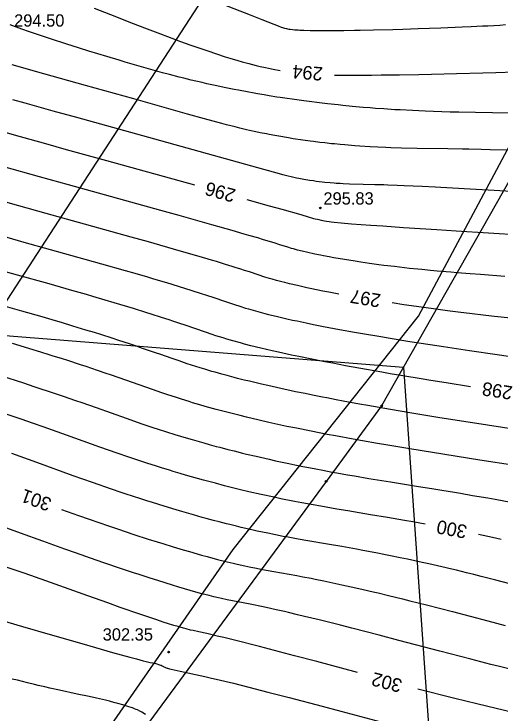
# Model space of a CAD drawing. Extents: x 7477803 to 7478145, y 5500698 to 5500984.
# Drawn here: x 7477874.58 to 7477901.52, y 5500853.98 to 5500892.73 of the extents above; entities that cross this region are included whole.
import ezdxf

# ---------------------------------------------------------------- set-up
doc = ezdxf.new("R2010")
doc.units = 0
for name, color, linetype in [('203-Punkt załamania granicy działki nie stabilizowany', 7, 'Continuous'), ('eWN', 7, 'Continuous'), ('gr_dzialki', 7, 'Continuous'), ('gr_klasy', 7, 'Continuous'), ('pkt_wys', 7, 'Continuous'), ('warst_ciagla', 7, 'Continuous'), ('warst_opis', 7, 'Continuous'), ('warst_pogrub', 7, 'Continuous'), ('warst_przeryw', 7, 'Continuous')]:
    doc.layers.add(name, color=color, linetype=linetype)

# ---------------------------------------------------------------- blocks, each defined once
blk = doc.blocks.new('203')
blk.add_circle((0, 0), 0.045)
blk = doc.blocks.new('801_3')
at = {"layer": 'pkt_wys'}
blk.add_circle((0, 0), 0.045, dxfattribs=at)
blk.add_circle((0, 0), 0.045, dxfattribs=at)

msp = doc.modelspace()

# ---------------------------------------------------------------- linework, layer by layer
at = {"layer": 'eWN'}
msp.add_lwpolyline([(7477864.586, 5500830.869), (7477874.504, 5500845.51), (7477886.717, 5500863.094), (7477896.968, 5500876.013), (7477903.181, 5500887.651), (7477907.573, 5500896.009), (7477910.052, 5500901.721), (7477911.094, 5500907.132), (7477899.209, 5500916.554), (7477885.259, 5500927.591), (7477881.972, 5500929.954), (7477875.911, 5500934.547), (7477875.795, 5500934.654)], dxfattribs=at)
at = {"layer": 'gr_dzialki'}
for points in [[(7477867.65, 5500866.83), (7477899.54, 5500915.94)], [(7477908.77, 5500895.48), (7477894.92, 5500871.04)], [(7477894.92, 5500871.04), (7477891.85, 5500866.86)], [(7477891.85, 5500866.86), (7477876.54, 5500846.03)]]:
    msp.add_lwpolyline(points, dxfattribs=at)
at = {"layer": 'gr_klasy'}
for points in [[(7477840.435, 5500877.607), (7477896.14, 5500873.19)], [(7477896.14, 5500873.19), (7477899.58, 5500823.8)]]:
    msp.add_lwpolyline(points, dxfattribs=at)
at = {"layer": 'warst_ciagla'}
for points in [[(7477879.025, 5500893.052), (7477879.924, 5500892.701), (7477881.178, 5500892.21), (7477881.798, 5500891.97), (7477882.689, 5500891.63), (7477883.069, 5500891.487), (7477883.56, 5500891.306), (7477883.798, 5500891.218), (7477884.319, 5500891.03), (7477884.981, 5500890.797), (7477885.304, 5500890.687), (7477885.784, 5500890.527), (7477886.269, 5500890.371), (7477886.515, 5500890.294), (7477886.966, 5500890.158), (7477887.203, 5500890.09), (7477887.577, 5500889.988), (7477887.982, 5500889.886), (7477888.199, 5500889.836), (7477888.504, 5500889.768), (7477888.664, 5500889.735), (7477888.915, 5500889.684), (7477889.317, 5500889.609)], [(7477892.306, 5500889.354), (7477892.728, 5500889.351), (7477893.559, 5500889.349), (7477894.37, 5500889.353), (7477894.896, 5500889.357), (7477895.909, 5500889.37), (7477896.982, 5500889.388), (7477897.674, 5500889.401), (7477899.066, 5500889.435), (7477900.519, 5500889.475), (7477901.244, 5500889.497), (7477902.289, 5500889.532)], [(7477873.093, 5500886.469), (7477874.585, 5500886.046), (7477876.329, 5500885.556), (7477877.474, 5500885.236), (7477879.697, 5500884.618), (7477884.565, 5500883.269)], [(7477892.549, 5500877.23), (7477892.007, 5500877.332), (7477891.671, 5500877.398), (7477891.059, 5500877.522), (7477890.78, 5500877.581), (7477890.274, 5500877.694), (7477889.829, 5500877.799), (7477889.564, 5500877.865), (7477889.399, 5500877.907), (7477889.097, 5500877.988), (7477888.867, 5500878.052), (7477888.725, 5500878.093), (7477888.459, 5500878.173), (7477888.091, 5500878.29), (7477887.604, 5500878.451), (7477887.339, 5500878.538), (7477887.123, 5500878.607), (7477886.812, 5500878.706), (7477886.645, 5500878.758), (7477886.292, 5500878.867), (7477885.777, 5500879.023), (7477885.502, 5500879.105), (7477884.836, 5500879.302), (7477883.721, 5500879.627), (7477882.015, 5500880.113), (7477881.068, 5500880.38), (7477876.367, 5500881.69), (7477874.851, 5500882.116), (7477872.954, 5500882.653)], [(7477887.456, 5500882.466), (7477888.704, 5500882.119), (7477889.409, 5500881.921), (7477890.446, 5500881.628), (7477890.864, 5500881.507), (7477891.097, 5500881.437), (7477891.153, 5500881.421), (7477891.24, 5500881.398), (7477891.376, 5500881.366), (7477891.453, 5500881.349), (7477891.579, 5500881.324), (7477891.768, 5500881.29), (7477891.872, 5500881.272), (7477892.026, 5500881.248), (7477892.121, 5500881.234), (7477892.299, 5500881.213), (7477892.684, 5500881.174), (7477893.254, 5500881.126), (7477894.318, 5500881.046), (7477894.981, 5500880.999), (7477896.137, 5500880.92), (7477897.983, 5500880.799), (7477899.036, 5500880.731), (7477902.624, 5500880.502)], [(7477899.834, 5500872.098), (7477898.484, 5500872.31), (7477897.644, 5500872.445), (7477897.109, 5500872.532), (7477896.099, 5500872.7), (7477895.39, 5500872.821), (7477894.939, 5500872.899), (7477894.088, 5500873.049), (7477892.927, 5500873.262), (7477892.224, 5500873.395), (7477891.784, 5500873.48), (7477890.966, 5500873.643), (7477890.333, 5500873.772), (7477889.938, 5500873.855), (7477889.208, 5500874.013), (7477888.871, 5500874.088), (7477888.247, 5500874.233), (7477887.682, 5500874.372), (7477887.335, 5500874.462), (7477887.114, 5500874.52), (7477886.697, 5500874.636), (7477886.366, 5500874.733), (7477886.154, 5500874.797), (7477885.749, 5500874.924), (7477885.554, 5500874.988), (7477885.173, 5500875.115), (7477884.053, 5500875.499), (7477883.764, 5500875.597), (7477883.367, 5500875.73), (7477883.164, 5500875.797), (7477882.748, 5500875.933), (7477882.175, 5500876.116), (7477881.881, 5500876.209), (7477881.198, 5500876.422), (7477880.122, 5500876.749), (7477879.624, 5500876.898), (7477878.941, 5500877.099), (7477878.591, 5500877.201), (7477877.784, 5500877.433), (7477876.525, 5500877.789), (7477874.785, 5500878.276), (7477873.902, 5500878.524)], [(7477902.061, 5500875.897), (7477901.168, 5500875.993), (7477900.692, 5500876.046), (7477899.787, 5500876.152), (7477899.309, 5500876.211), (7477898.564, 5500876.305), (7477897.786, 5500876.408), (7477897.386, 5500876.463), (7477896.566, 5500876.579), (7477896.147, 5500876.641), (7477895.508, 5500876.737)], [(7477902.285, 5500867.731), (7477900.354, 5500868.042), (7477897.741, 5500868.46), (7477896.473, 5500868.666), (7477895.262, 5500868.866), (7477894.687, 5500868.963), (7477893.866, 5500869.104), (7477893.346, 5500869.196), (7477892.367, 5500869.373), (7477891.904, 5500869.46), (7477891.027, 5500869.63), (7477890.204, 5500869.796), (7477889.681, 5500869.906), (7477889.342, 5500869.979), (7477888.681, 5500870.125), (7477888.139, 5500870.249), (7477887.437, 5500870.416), (7477887.095, 5500870.5), (7477886.427, 5500870.67), (7477886.138, 5500870.745), (7477885.759, 5500870.847), (7477885.573, 5500870.898), (7477885.161, 5500871.013), (7477884.859, 5500871.1), (7477884.466, 5500871.216), (7477884.273, 5500871.274), (7477883.848, 5500871.407), (7477883.571, 5500871.495), (7477883.032, 5500871.672), (7477882.769, 5500871.761), (7477882.253, 5500871.938), (7477880.767, 5500872.46), (7477880.404, 5500872.587), (7477879.922, 5500872.754), (7477879.682, 5500872.836), (7477879.205, 5500872.998), (7477878.573, 5500873.21), (7477878.26, 5500873.314), (7477877.56, 5500873.542), (7477877.213, 5500873.654), (7477876.752, 5500873.8), (7477876.523, 5500873.872), (7477876.068, 5500874.014), (7477875.466, 5500874.198), (7477875.167, 5500874.288), (7477874.499, 5500874.486)], [(7477877.202, 5500865.3), (7477878.15, 5500864.965), (7477878.738, 5500864.76), (7477879.812, 5500864.391), (7477880.303, 5500864.225), (7477881.204, 5500863.927), (7477882.008, 5500863.667), (7477882.499, 5500863.512), (7477882.809, 5500863.416), (7477883.394, 5500863.238), (7477883.95, 5500863.071), (7477884.3, 5500862.969), (7477884.956, 5500862.782), (7477885.263, 5500862.697), (7477885.84, 5500862.542), (7477886.375, 5500862.406), (7477886.711, 5500862.325), (7477886.928, 5500862.275), (7477887.345, 5500862.182), (7477887.684, 5500862.11), (7477887.904, 5500862.066), (7477888.335, 5500861.983), (7477888.966, 5500861.868), (7477889.805, 5500861.72), (7477890.236, 5500861.643), (7477890.567, 5500861.581), (7477891.021, 5500861.493), (7477891.253, 5500861.447), (7477891.728, 5500861.351), (7477892.383, 5500861.213), (7477892.72, 5500861.14), (7477893.501, 5500860.967), (7477893.903, 5500860.875), (7477894.452, 5500860.748), (7477894.731, 5500860.682), (7477895.301, 5500860.546), (7477896.082, 5500860.355), (7477896.482, 5500860.255), (7477897.405, 5500860.022), (7477898.841, 5500859.65), (7477900.789, 5500859.139), (7477901.747, 5500858.889)], [(7477893.589, 5500856.284), (7477891.333, 5500856.881), (7477890.098, 5500857.205), (7477888.156, 5500857.71), (7477886.85, 5500858.043), (7477886.188, 5500858.209), (7477885.826, 5500858.297), (7477885.26, 5500858.431), (7477884.81, 5500858.53), (7477884.497, 5500858.597), (7477884.347, 5500858.631), (7477884.105, 5500858.691), (7477883.968, 5500858.728), (7477883.767, 5500858.785), (7477883.658, 5500858.817), (7477883.424, 5500858.887), (7477883.078, 5500858.995), (7477882.89, 5500859.055), (7477882.433, 5500859.204), (7477881.656, 5500859.466), (7477881.275, 5500859.597), (7477880.733, 5500859.785), (7477880.448, 5500859.886), (7477879.77, 5500860.126), (7477878.671, 5500860.52), (7477877.118, 5500861.078), (7477876.337, 5500861.357), (7477875.193, 5500861.759), (7477874.696, 5500861.931), (7477874.045, 5500862.155)], [(7477881.867, 5500853.962), (7477881.663, 5500854.078), (7477881.548, 5500854.14), (7477881.415, 5500854.203), (7477881.339, 5500854.236), (7477881.256, 5500854.27), (7477881.135, 5500854.315), (7477881.069, 5500854.339), (7477880.928, 5500854.386), (7477880.721, 5500854.452), (7477880.608, 5500854.485), (7477880.335, 5500854.563), (7477880.187, 5500854.602), (7477879.979, 5500854.657), (7477879.87, 5500854.684), (7477879.643, 5500854.74), (7477879.319, 5500854.817), (7477879.149, 5500854.856), (7477878.746, 5500854.946), (7477878.086, 5500855.087), (7477877.107, 5500855.296), (7477876.574, 5500855.414), (7477876.297, 5500855.478), (7477875.917, 5500855.567), (7477875.722, 5500855.613), (7477875.323, 5500855.71), (7477874.771, 5500855.846), (7477874.487, 5500855.918)], [(7477902.26, 5500854.048), (7477900.187, 5500854.55), (7477898.977, 5500854.845), (7477896.921, 5500855.351)]]:
    msp.add_lwpolyline(points, dxfattribs=at)
at = {"layer": 'warst_pogrub'}
for points in [[(7477902.022, 5500885.194), (7477900.935, 5500885.222), (7477900.432, 5500885.233), (7477899.744, 5500885.247), (7477899.391, 5500885.253), (7477898.579, 5500885.266), (7477896.884, 5500885.292), (7477896.017, 5500885.311), (7477895.438, 5500885.329), (7477895.149, 5500885.339), (7477894.718, 5500885.358), (7477894.289, 5500885.381), (7477893.722, 5500885.417), (7477893.44, 5500885.437), (7477892.881, 5500885.482), (7477892.634, 5500885.505), (7477892.306, 5500885.537), (7477892.143, 5500885.553), (7477891.778, 5500885.593), (7477891.505, 5500885.625), (7477891.144, 5500885.67), (7477890.964, 5500885.694), (7477890.562, 5500885.749), (7477890.03, 5500885.829), (7477889.766, 5500885.872), (7477889.242, 5500885.962), (7477889.01, 5500886.004), (7477888.704, 5500886.062), (7477888.551, 5500886.092), (7477888.209, 5500886.161), (7477887.954, 5500886.215), (7477887.617, 5500886.29), (7477887.449, 5500886.328), (7477887.073, 5500886.417), (7477886.824, 5500886.478), (7477886.33, 5500886.604), (7477886.085, 5500886.668), (7477885.6, 5500886.799), (7477885.121, 5500886.931), (7477884.182, 5500887.196), (7477881.211, 5500888.036), (7477878.547, 5500888.782), (7477876.237, 5500889.423), (7477874.474, 5500889.915)], [(7477897.33, 5500864.49), (7477896.647, 5500864.612), (7477896.183, 5500864.693), (7477895.243, 5500864.853), (7477894.298, 5500865.012), (7477893.05, 5500865.221), (7477892.44, 5500865.324), (7477891.553, 5500865.479), (7477891.125, 5500865.555), (7477890.507, 5500865.67), (7477890.11, 5500865.746), (7477889.345, 5500865.899), (7477888.976, 5500865.976), (7477888.261, 5500866.131), (7477887.569, 5500866.289), (7477887.117, 5500866.397), (7477886.819, 5500866.471), (7477886.226, 5500866.62), (7477885.727, 5500866.751), (7477885.063, 5500866.93), (7477884.732, 5500867.022), (7477884.069, 5500867.212), (7477883.775, 5500867.298), (7477883.384, 5500867.415), (7477883.188, 5500867.474), (7477882.748, 5500867.61), (7477882.419, 5500867.714), (7477881.98, 5500867.855), (7477881.761, 5500867.926), (7477881.268, 5500868.09), (7477880.94, 5500868.2), (7477880.289, 5500868.424), (7477879.326, 5500868.762), (7477877.481, 5500869.421), (7477876.2, 5500869.875), (7477875.661, 5500870.064), (7477874.971, 5500870.303), (7477874.639, 5500870.418), (7477873.922, 5500870.662)], [(7477901.539, 5500863.64), (7477901.057, 5500863.749), (7477900.275, 5500863.921)]]:
    msp.add_lwpolyline(points, dxfattribs=at)
at = {"layer": 'warst_przeryw'}
for points in [[(7477884.938, 5500893.751), (7477887.644, 5500892.684), (7477888.29, 5500892.431), (7477888.952, 5500892.173), (7477889.197, 5500892.079), (7477889.371, 5500892.013), (7477889.446, 5500891.987), (7477889.552, 5500891.953), (7477889.656, 5500891.925), (7477889.709, 5500891.914), (7477889.794, 5500891.899), (7477889.856, 5500891.89), (7477889.993, 5500891.874), (7477890.113, 5500891.863), (7477890.297, 5500891.851), (7477890.399, 5500891.846), (7477890.623, 5500891.837), (7477890.963, 5500891.827), (7477891.151, 5500891.824), (7477891.618, 5500891.819), (7477891.874, 5500891.819), (7477892.239, 5500891.82), (7477892.431, 5500891.821), (7477892.837, 5500891.825), (7477893.419, 5500891.833), (7477893.728, 5500891.838), (7477894.467, 5500891.853), (7477895.537, 5500891.88), (7477896.096, 5500891.896), (7477896.945, 5500891.922), (7477898.2, 5500891.966), (7477899.376, 5500892.015), (7477899.869, 5500892.038), (7477900.499, 5500892.07), (7477900.802, 5500892.086), (7477901.455, 5500892.124), (7477901.766, 5500892.144)], [(7477902.906, 5500887.238), (7477901.054, 5500887.262), (7477900.122, 5500887.277), (7477899.188, 5500887.296), (7477898.722, 5500887.307), (7477897.792, 5500887.336), (7477897.329, 5500887.353), (7477896.637, 5500887.383), (7477895.95, 5500887.419), (7477895.646, 5500887.437), (7477895.242, 5500887.463), (7477895.041, 5500887.476), (7477894.59, 5500887.509), (7477894.29, 5500887.532), (7477893.892, 5500887.565), (7477893.693, 5500887.582), (7477893.298, 5500887.618), (7477892.772, 5500887.669), (7477892.511, 5500887.696), (7477891.926, 5500887.76), (7477891.489, 5500887.811), (7477890.91, 5500887.883), (7477890.622, 5500887.92), (7477889.977, 5500888.01), (7477889.692, 5500888.051), (7477889.313, 5500888.109), (7477889.125, 5500888.138), (7477888.702, 5500888.206), (7477888.421, 5500888.253), (7477888.048, 5500888.317), (7477887.862, 5500888.35), (7477887.491, 5500888.417), (7477887, 5500888.511), (7477886.755, 5500888.558), (7477886.207, 5500888.67), (7477885.799, 5500888.756), (7477885.258, 5500888.876), (7477884.989, 5500888.937), (7477884.386, 5500889.079), (7477883.987, 5500889.177), (7477883.722, 5500889.244), (7477883.195, 5500889.38), (7477882.802, 5500889.484), (7477882.021, 5500889.698), (7477881.248, 5500889.919), (7477880.736, 5500890.068), (7477880.396, 5500890.169), (7477879.721, 5500890.372), (7477878.715, 5500890.683), (7477878.21, 5500890.842), (7477877.445, 5500891.087), (7477876.664, 5500891.344), (7477876.265, 5500891.477), (7477875.444, 5500891.755), (7477875.021, 5500891.901), (7477874.368, 5500892.129)], [(7477902.765, 5500882.862), (7477900.823, 5500882.979), (7477899.488, 5500883.056), (7477897.888, 5500883.141), (7477897.165, 5500883.178), (7477896.176, 5500883.223), (7477895.773, 5500883.24), (7477895.272, 5500883.26), (7477895.036, 5500883.268), (7477894.543, 5500883.284), (7477893.893, 5500883.3), (7477893.145, 5500883.32), (7477892.799, 5500883.334), (7477892.628, 5500883.343), (7477892.403, 5500883.357), (7477892.291, 5500883.365), (7477892.068, 5500883.383), (7477891.775, 5500883.411), (7477891.63, 5500883.427), (7477891.306, 5500883.467), (7477891.146, 5500883.489), (7477890.935, 5500883.521), (7477890.83, 5500883.538), (7477890.621, 5500883.574), (7477890.347, 5500883.625), (7477890.211, 5500883.653), (7477889.909, 5500883.719), (7477889.759, 5500883.755), (7477889.456, 5500883.831), (7477889.138, 5500883.916), (7477888.4, 5500884.122), (7477885.959, 5500884.804), (7477882.381, 5500885.797), (7477878.053, 5500886.996), (7477876.745, 5500887.36), (7477875.208, 5500887.791), (7477874.527, 5500887.982)], [(7477901.73, 5500878.206), (7477900.391, 5500878.304), (7477899.825, 5500878.348), (7477899.099, 5500878.407), (7477898.747, 5500878.436), (7477897.985, 5500878.504), (7477897.619, 5500878.538), (7477897.146, 5500878.583), (7477896.917, 5500878.606), (7477896.471, 5500878.653), (7477895.904, 5500878.715), (7477895.633, 5500878.746), (7477895.051, 5500878.817), (7477894.775, 5500878.852), (7477894.251, 5500878.924), (7477893.762, 5500878.996), (7477893.453, 5500879.044), (7477892.871, 5500879.138), (7477892.268, 5500879.243), (7477892.017, 5500879.288), (7477891.698, 5500879.348), (7477891.546, 5500879.378), (7477891.22, 5500879.443), (7477890.774, 5500879.54), (7477890.592, 5500879.582), (7477890.367, 5500879.637), (7477890.261, 5500879.664), (7477890.039, 5500879.725), (7477889.937, 5500879.755), (7477889.738, 5500879.816), (7477889.283, 5500879.963), (7477888.982, 5500880.058), (7477888.386, 5500880.238), (7477888.064, 5500880.334), (7477887.578, 5500880.476), (7477887.312, 5500880.553), (7477886.655, 5500880.742), (7477885.52, 5500881.065), (7477883.727, 5500881.57), (7477882.711, 5500881.853), (7477877.6, 5500883.274), (7477875.988, 5500883.724), (7477874.028, 5500884.276)], [(7477874.182, 5500880.375), (7477875.135, 5500880.107), (7477876.588, 5500879.701), (7477878.507, 5500879.165), (7477879.426, 5500878.907), (7477880.724, 5500878.536), (7477881.269, 5500878.379), (7477881.964, 5500878.176), (7477882.298, 5500878.077), (7477883.017, 5500877.862), (7477884.011, 5500877.559), (7477884.421, 5500877.431), (7477884.936, 5500877.267), (7477885.18, 5500877.189), (7477885.696, 5500877.019), (7477886.171, 5500876.858), (7477886.775, 5500876.654), (7477887.079, 5500876.555), (7477887.393, 5500876.456), (7477887.556, 5500876.407), (7477887.811, 5500876.332), (7477888.08, 5500876.257), (7477888.461, 5500876.156), (7477888.661, 5500876.105), (7477889.081, 5500876.002), (7477889.681, 5500875.863), (7477889.998, 5500875.792), (7477890.243, 5500875.739), (7477890.58, 5500875.667), (7477890.753, 5500875.631), (7477891.153, 5500875.55), (7477891.708, 5500875.44), (7477891.995, 5500875.384), (7477892.589, 5500875.273), (7477893.421, 5500875.122), (7477893.854, 5500875.045), (7477894.87, 5500874.871), (7477895.4, 5500874.783), (7477896.49, 5500874.607), (7477897.601, 5500874.432), (7477898.341, 5500874.319), (7477899.786, 5500874.101), (7477901.309, 5500873.88), (7477901.947, 5500873.79)], [(7477902.675, 5500869.672), (7477899.7, 5500870.136), (7477898.143, 5500870.384), (7477896.598, 5500870.636), (7477895.843, 5500870.763), (7477895.107, 5500870.889), (7477894.156, 5500871.056), (7477893.692, 5500871.139), (7477892.792, 5500871.305), (7477892.403, 5500871.378), (7477891.894, 5500871.476), (7477891.644, 5500871.524), (7477891.093, 5500871.633), (7477890.69, 5500871.715), (7477890.165, 5500871.823), (7477889.909, 5500871.877), (7477889.345, 5500871.999), (7477888.624, 5500872.159), (7477888.276, 5500872.239), (7477887.606, 5500872.399), (7477887.319, 5500872.469), (7477886.947, 5500872.563), (7477886.765, 5500872.609), (7477886.368, 5500872.714), (7477886.08, 5500872.793), (7477885.709, 5500872.897), (7477885.529, 5500872.949), (7477885.138, 5500873.065), (7477884.887, 5500873.142), (7477884.404, 5500873.296), (7477884.17, 5500873.373), (7477883.717, 5500873.526), (7477883.276, 5500873.678), (7477882.699, 5500873.879), (7477882.41, 5500873.98), (7477882.084, 5500874.092), (7477881.644, 5500874.242), (7477881.423, 5500874.317), (7477880.976, 5500874.465), (7477880.374, 5500874.663), (7477880.07, 5500874.762), (7477879.379, 5500874.982), (7477879.029, 5500875.092), (7477878.559, 5500875.238), (7477878.323, 5500875.311), (7477877.846, 5500875.456), (7477877.203, 5500875.649), (7477876.879, 5500875.745), (7477876.879, 5500875.745), (7477876.142, 5500875.96), (7477875.016, 5500876.281), (7477872.67, 5500876.94)], [(7477874.183, 5500872.606), (7477874.761, 5500872.422), (7477875.057, 5500872.326), (7477875.741, 5500872.102), (7477876.813, 5500871.743), (7477877.308, 5500871.574), (7477877.984, 5500871.341), (7477878.329, 5500871.22), (7477879.124, 5500870.941), (7477880.789, 5500870.35), (7477881.66, 5500870.048), (7477882.256, 5500869.848), (7477882.558, 5500869.748), (7477883.017, 5500869.6), (7477883.482, 5500869.455), (7477884.114, 5500869.264), (7477884.434, 5500869.171), (7477885.084, 5500868.986), (7477885.377, 5500868.905), (7477885.77, 5500868.799), (7477885.969, 5500868.747), (7477886.42, 5500868.63), (7477886.761, 5500868.543), (7477887.221, 5500868.429), (7477887.454, 5500868.373), (7477887.981, 5500868.248), (7477888.694, 5500868.085), (7477889.056, 5500868.005), (7477889.787, 5500867.848), (7477890.116, 5500867.779), (7477890.559, 5500867.689), (7477890.782, 5500867.645), (7477891.287, 5500867.546), (7477891.67, 5500867.473), (7477892.185, 5500867.377), (7477892.444, 5500867.33), (7477893.032, 5500867.226), (7477893.427, 5500867.158), (7477894.22, 5500867.024), (7477895.406, 5500866.829), (7477896.953, 5500866.58), (7477897.699, 5500866.46), (7477898.243, 5500866.372), (7477898.944, 5500866.255), (7477899.286, 5500866.198), (7477899.949, 5500866.086), (7477900.792, 5500865.939), (7477901.197, 5500865.867), (7477902.065, 5500865.71)], [(7477903.638, 5500860.768), (7477901.247, 5500861.391), (7477900.43, 5500861.6), (7477900.021, 5500861.703), (7477899.612, 5500861.804), (7477899.068, 5500861.936), (7477898.796, 5500862.001), (7477898.252, 5500862.128), (7477897.529, 5500862.292), (7477897.167, 5500862.373), (7477896.356, 5500862.548), (7477895.95, 5500862.633), (7477895.411, 5500862.743), (7477895.141, 5500862.797), (7477894.603, 5500862.903), (7477893.886, 5500863.039), (7477893.528, 5500863.105), (7477892.724, 5500863.248), (7477891.92, 5500863.386), (7477890.842, 5500863.568), (7477890.297, 5500863.663), (7477889.745, 5500863.763), (7477889.467, 5500863.815), (7477889.045, 5500863.898), (7477888.617, 5500863.985), (7477888.039, 5500864.11), (7477887.746, 5500864.175), (7477887.152, 5500864.313), (7477886.885, 5500864.378), (7477886.527, 5500864.466), (7477886.346, 5500864.512), (7477885.936, 5500864.617), (7477885.626, 5500864.698), (7477885.209, 5500864.81), (7477884.998, 5500864.868), (7477884.521, 5500865.001), (7477883.876, 5500865.187), (7477883.55, 5500865.283), (7477883.55, 5500865.283), (7477882.89, 5500865.483), (7477882.594, 5500865.574), (7477882.196, 5500865.699), (7477881.996, 5500865.763), (7477881.542, 5500865.909), (7477881.198, 5500866.021), (7477880.737, 5500866.174), (7477880.504, 5500866.252), (7477879.978, 5500866.431), (7477878.917, 5500866.8), (7477877.862, 5500867.174), (7477875.838, 5500867.902), (7477874.459, 5500868.395)], [(7477902.386, 5500856.365), (7477901.444, 5500856.602), (7477900.963, 5500856.725), (7477899.857, 5500857.009), (7477898.148, 5500857.456), (7477895.875, 5500858.056), (7477894.789, 5500858.341), (7477893.27, 5500858.733), (7477892.639, 5500858.893), (7477891.84, 5500859.094), (7477891.459, 5500859.188), (7477890.646, 5500859.386), (7477890.262, 5500859.478), (7477889.775, 5500859.593), (7477889.541, 5500859.647), (7477889.095, 5500859.749), (7477888.542, 5500859.871), (7477888.284, 5500859.926), (7477887.748, 5500860.037), (7477887.268, 5500860.13), (7477886.672, 5500860.243), (7477886.374, 5500860.302), (7477886.064, 5500860.368), (7477885.901, 5500860.405), (7477885.645, 5500860.465), (7477885.372, 5500860.533), (7477884.98, 5500860.636), (7477884.772, 5500860.693), (7477884.332, 5500860.818), (7477883.697, 5500861.005), (7477883.358, 5500861.108), (7477882.543, 5500861.363), (7477882.109, 5500861.503), (7477881.502, 5500861.701), (7477881.187, 5500861.805), (7477880.533, 5500862.025), (7477879.611, 5500862.339), (7477879.129, 5500862.506), (7477877.992, 5500862.904), (7477877.398, 5500863.114), (7477876.174, 5500863.552), (7477874.934, 5500863.999), (7477872.553, 5500864.862)], [(7477872.727, 5500859.509), (7477875.047, 5500858.832), (7477876.589, 5500858.383), (7477878.339, 5500857.877), (7477879.083, 5500857.663), (7477880.035, 5500857.392), (7477881, 5500857.123), (7477881.352, 5500857.028), (7477881.725, 5500856.932), (7477881.895, 5500856.891), (7477882.125, 5500856.84), (7477882.262, 5500856.809), (7477882.422, 5500856.77), (7477882.492, 5500856.752), (7477882.584, 5500856.725), (7477882.684, 5500856.692), (7477882.724, 5500856.676), (7477882.772, 5500856.654), (7477882.845, 5500856.613), (7477882.881, 5500856.594), (7477882.931, 5500856.57), (7477882.957, 5500856.558), (7477882.997, 5500856.541), (7477883.053, 5500856.52), (7477883.083, 5500856.511), (7477883.191, 5500856.479), (7477883.28, 5500856.458), (7477883.775, 5500856.346), (7477884.626, 5500856.163), (7477885.134, 5500856.054), (7477885.443, 5500855.985), (7477886.009, 5500855.853), (7477886.725, 5500855.679), (7477887.923, 5500855.379), (7477888.627, 5500855.198), (7477889.813, 5500854.891), (7477891.638, 5500854.413), (7477892.656, 5500854.144), (7477894.874, 5500853.555)]]:
    msp.add_lwpolyline(points, dxfattribs=at)

# ---------------------------------------------------------------- block references
at = {"layer": '203-Punkt załamania granicy działki nie stabilizowany'}
for p in [(7477894.92, 5500871.04), (7477891.85, 5500866.86)]:
    msp.add_blockref('203', p, dxfattribs=at)
at = {"layer": 'pkt_wys', "rotation": 0.0626175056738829}
for p in [(7477891.532, 5500881.997), (7477883.139, 5500857.408)]:
    msp.add_blockref('801_3', p, dxfattribs=at)

# ---------------------------------------------------------------- texts
at = {"layer": 'pkt_wys'}
for s, p in [('294.50', (7477874.59, 5500892.033)), ('295.83', (7477891.701, 5500882.182)), ('302.35', (7477879.49, 5500858.045))]:
    msp.add_text(s, height=0.68, rotation=0.0626, dxfattribs=at).set_placement(p)
at = {"layer": 'warst_opis'}
for s, rotation, p in [('294', 175.1302, (7477891.691, 5500889.782)), ('296', 164.4798, (7477886.901, 5500883.01)), ('297', 170.5426, (7477894.914, 5500877.216)), ('298', 171.2409, (7477902.2, 5500872.113)), ('301', 160.1759, (7477876.721, 5500865.89)), ('300', 169.0647, (7477899.694, 5500864.416)), ('302', 165.1203, (7477896.109, 5500855.877))]:
    msp.add_text(s, height=0.75, rotation=rotation, dxfattribs=at).set_placement(p)

doc.saveas('drawing.dxf')
